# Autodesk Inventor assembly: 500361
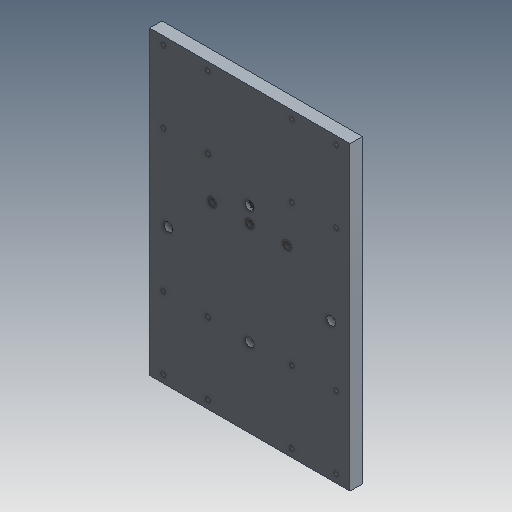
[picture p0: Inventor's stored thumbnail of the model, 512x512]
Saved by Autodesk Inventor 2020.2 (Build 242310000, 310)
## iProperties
Created: 2000-02
Part Number: 500361
Document SubType Name: Assembly
Description: PLT-XX,FA,CP,05,120,080,PLATE,BUCKET_CARRIAGE
Designer: glanglot
Mass: 2097.65 g
Surface Area: 1475.74 cm^2
Volume: 767.213 cm^3
Density: 2.73412 g/cm^3
Control State: 0
Checked Out: False
Master: False
Shininess: 0.0
Length Units: 11269
Angle Units: 11279
Time Units: 11290
Mass Units: 11283
Length Display Precision: 3
Angle Display Precision: 2
Compacted: True
Dimensions: 305x12,5x203 mm
Mass: 2,098 kg
DocNumber: 500361.iam
Folder: 01 - Themengebiete\Simplification\01 - Packaging machine\
VDS_Category: 3D Komponenten
Density: 0.0
Volumn: 0.0
Area: 0.0
PropertySet Name: Model Information
Author: glanglot
Revision Number: -
Title: plate
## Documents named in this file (4)
- D:\07 - DEMODATEN\OTX 2019 - Dataset - UPDATE - Dez2019\Designs\07-Packing machine\500361.iam
- D:\07 - DEMODATEN\OTX 2019 - Dataset - UPDATE - Dez2019\Designs\07-Packing machine\Parts\ADSK-011735.ipt
- D:\07 - DEMODATEN\OTX 2019 - Dataset - UPDATE - Dez2019\Designs\07-Packing machine\Parts\ADSK-011345.ipt
- D:\07 - DEMODATEN\OTX 2019 - Dataset - UPDATE - Dez2019\Designs\07-Packing machine\Parts\ADSK-011736.ipt
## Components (21 placed, 3 different names)
1. ADSK-011345:1 — Insert:1, Insert:2, Insert:3, Insert:4, Insert:5, Insert:6, Insert:7, Insert:8, Insert:9, Insert:10, Insert:11, Insert:12, Insert:13, Insert:14, Insert:15, Insert:16, Insert:17, Insert:18, Insert:19, Insert:20
2. ADSK-011735:1 — Insert:1
3. ADSK-011735:2 — Insert:2
4. ADSK-011735:3 — Insert:3
5. ADSK-011735:4 — Insert:4
6. ADSK-011735:5 — Insert:6
7. ADSK-011735:6 — Insert:5
8. ADSK-011735:7 — Insert:7
9. ADSK-011735:8 — Insert:8
10. ADSK-011735:9 — Insert:10
11. ADSK-011735:10 — Insert:9
12. ADSK-011735:11 — Insert:11
13. ADSK-011735:12 — Insert:12
14. ADSK-011735:13 — Insert:16
15. ADSK-011735:14 — Insert:15
16. ADSK-011735:15 — Insert:14
17. ADSK-011735:16 — Insert:13
18. ADSK-011736:1 — Insert:17
19. ADSK-011736:2 — Insert:18
20. ADSK-011736:3 — Insert:19
21. ADSK-011736:4 — Insert:20
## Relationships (20: Insert 20)
- Insert:1: ADSK-011345:1 ↔ ADSK-011735:1
- Insert:2: ADSK-011345:1 ↔ ADSK-011735:2
- Insert:3: ADSK-011345:1 ↔ ADSK-011735:3
- Insert:4: ADSK-011345:1 ↔ ADSK-011735:4
- Insert:5: ADSK-011345:1 ↔ ADSK-011735:6
- Insert:6: ADSK-011345:1 ↔ ADSK-011735:5
- Insert:7: ADSK-011345:1 ↔ ADSK-011735:7
- Insert:8: ADSK-011345:1 ↔ ADSK-011735:8
- Insert:9: ADSK-011345:1 ↔ ADSK-011735:10
- Insert:10: ADSK-011345:1 ↔ ADSK-011735:9
- Insert:11: ADSK-011345:1 ↔ ADSK-011735:11
- Insert:12: ADSK-011345:1 ↔ ADSK-011735:12
- Insert:13: ADSK-011345:1 ↔ ADSK-011735:16
- Insert:14: ADSK-011345:1 ↔ ADSK-011735:15
- Insert:15: ADSK-011345:1 ↔ ADSK-011735:14
- Insert:16: ADSK-011345:1 ↔ ADSK-011735:13
- Insert:17: ADSK-011345:1 ↔ ADSK-011736:1
- Insert:18: ADSK-011345:1 ↔ ADSK-011736:2
- Insert:19: ADSK-011345:1 ↔ ADSK-011736:3
- Insert:20: ADSK-011345:1 ↔ ADSK-011736:4
